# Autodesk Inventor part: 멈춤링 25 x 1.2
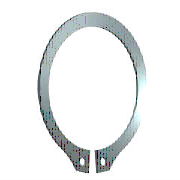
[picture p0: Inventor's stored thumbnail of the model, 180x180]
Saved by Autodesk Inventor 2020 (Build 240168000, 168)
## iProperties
IsCustomPart: 1
Created: 2009-02
Part Number: 멈춤링 25 x 1.2
Material: 강, 연강
Description: 리테이닝 링(C형)
Document SubType Name: Modeling
Standard: KS B 1336
Designer: 진현석
Standards Organization: KS
Language: ko-KR
Size Designation: 25 x 1.2
Categories: <MemberInstance><Categories><Category DisplayName="샤프트 부품" InternalName="7f7aeb1f-a693-4053-b835-cee3144e0d98" Mnemonic="SHFT"><Category DisplayName="써클립" Inter
Density: 1 g/cm^3
Appearance: 강철(1)
Author: 진현석
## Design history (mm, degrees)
sketch "스케치1"
  geometry: L1 (-6, 0)-(6, 0) reference; L2 (0, 20.189)-(0, -80.536) reference; L3 (-48.09, 0)-(48.09, 0) reference; L4 (-0.5, -24.44)-(-0.5, -28.74); L5 (-0.5, -6.54)-(-0.5, -13.29); L6 (-2.795, 3.1)-(3.672, 3.1); L7 (0.5, -6.54)-(0.5, -13.29); L8 (0.5, -24.44)-(0.5, -28.74); C1 r 1 at (-2, -26.606); C2 r 1 at (2, -26.606); A1 r 11.95 centre (0, -12.5) between (0.5, -24.44) and (-0.5, -24.44); A2 r 14.825 centre (0, -11.725) between (5.202, -25.608) and (-5.202, -25.608); A3 r 16.247 centre (0, -12.5) between (-2.281, -28.586) and (-0.5, -28.74); A4 r 2 centre (-2, -26.606) between (-3.952, -27.043) and (-2.281, -28.586); A5 r 2 centre (-5.903, -27.48) between (-3.952, -27.043) and (-5.202, -25.608); A6 r 2 centre (5.903, -27.48) between (5.202, -25.608) and (3.952, -27.043); A7 r 2 centre (2, -26.606) between (2.281, -28.586) and (3.952, -27.043); A8 r 16.247 centre (0, -12.5) between (0.5, -28.74) and (2.281, -28.586)
  constraints: 16 point on circle, 12 end point, 10 centre point, 9 symmetric about line, 5 point on line, 4 tangent, 3 coincident, 2 horizontal, 1 perpendicular, 1 vertical, 5 other
  dimensions: "d0" = 23.9 diameter of A1 (= ND); "d1" = 4.3 distance of L4.end L4.start (= SRB2); "d6" = 0.5 distance between parallel lines of L2 L5 (= 0.25 x SD5); "d7" = 3.1 distance between parallel lines of L6 L3 (= SRB1); "d8" = 0.775 distance of A1.centre A2.centre (= 0.25 x SRB1); "d9" = 2 radius of A4 (= SD5); "d10" = 2 radius of A5 (= SD5); "d11" = 1.5 distance from line of L4 A4.centre (= 0.75 x SD5); "d12" = 2 diameter of C1 (= SD5); "d13" = 2 diameter of C2 (= SD5); "d14" = 12.5 distance from line of A1.centre L1 (= 0.5 x WD)
extrude "본체" new body sketch "스케치1" distance "d2" = 1.2 (= SD); taper "d3" = 0 deg
workaxis "Work Axis1"
workplane "Work Plane1"
body "Solid1"
other parameters: "WD" = 25 (= WDMIN) [user parameter; used in 1 equation term], "SD" = 1.2 [user parameter; used in 1 equation term], "SRB1" = 3.1 [user parameter; used in 2 equation terms], "ND" = 23.9 [user parameter; used in 1 equation term], "SRB2" = 4.3 [user parameter; used in 1 equation term], "SD5" = 2 [user parameter; used in 6 equation terms], "d15" = 0, "d16" = 0, "d17" = 0, "d41" = 0, "d42" = 0, "WDMIN" = 25 [user parameter; used in 1 equation term], "SD3" = 23.2 [user parameter], "WDMAX" = 26 [user parameter]
